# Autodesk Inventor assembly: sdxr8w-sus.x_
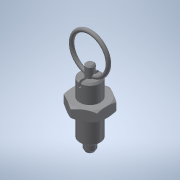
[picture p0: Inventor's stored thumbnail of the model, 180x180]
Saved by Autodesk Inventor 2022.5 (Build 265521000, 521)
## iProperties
Part Number: sdxr8w-sus.x_
Material: 一般
Document SubType Name: Assembly
Designer: ImaoCorp
Sending System: SOLIDWORKS 2017-2017317
MC: AMD64
MC_MODEL: Intel64 Family 6 Model 60 Stepping 3, GenuineIntel
OS: Windows_NT
FRU: Parasolid Version 29.0, build 201,  4-17-2017
FORMAT: text
GUISE: transmit
KEY: sdxr8w-sus
FILE: sdxr8w-sus.x_t
DATE: Wed Sep 18 16:15:16 2019
Author: ImaoCorp
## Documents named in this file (3)
- X:\14_SW2022-Inv2022\00_全2023-1023新製品(TCC)まで\s\sdxr8w-sus\SDXR8W-SUS.iam
- X:\14_SW2022-Inv2022\00_全2023-1023新製品(TCC)まで\s\sdxr8w-sus\sdxr8w-sus_01.ipt
- X:\14_SW2022-Inv2022\00_全2023-1023新製品(TCC)まで\s\sdxr8w-sus\sdxr8w-sus_02.ipt
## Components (2 placed, 2 different names)
1. sdxr8w-sus_01
2. sdxr8w-sus_02
